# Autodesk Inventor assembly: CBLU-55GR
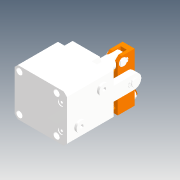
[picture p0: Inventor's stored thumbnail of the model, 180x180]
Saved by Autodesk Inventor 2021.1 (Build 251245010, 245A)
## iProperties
Created: 2019-05
Part Number: CBLU-55GR
Description: STEP AP214
Document SubType Name: Assembly
Designer: user
Title: CBLU-55GR.STEP
Revision Number: ÈÎºÎ
Sending System: SolidWorks 2016
Preprocessor: SwSTEP 2.0
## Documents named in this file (13)
- D:\Vault_2016\Projekty\Clamptek\Hydraulic\CBLU\CBLU-55\Inventor\CBLU-55GR\CBLU-55GR.iam
- D:\Vault_2016\Projekty\Clamptek\Hydraulic\CBLU\CBLU-55\Inventor\CBLU-55GR\CBLU-55CR±¾Ìå_2_1.ipt
- D:\Vault_2016\Projekty\Clamptek\Hydraulic\CBLU\CBLU-55\Inventor\CBLU-55GR\changxiao.ipt
- D:\Vault_2016\Projekty\Clamptek\Hydraulic\CBLU\CBLU-55\Inventor\CBLU-55GR\duanxiao.ipt
- D:\Vault_2016\Projekty\Clamptek\Hydraulic\CBLU\CBLU-55\Inventor\CBLU-55GR\huosaigan_5.ipt
- D:\Vault_2016\Projekty\Clamptek\Hydraulic\CBLU\CBLU-55\Inventor\CBLU-55GR\kahuang.ipt
- D:\Vault_2016\Projekty\Clamptek\Hydraulic\CBLU\CBLU-55\Inventor\CBLU-55GR\kahuang01.ipt
- D:\Vault_2016\Projekty\Clamptek\Hydraulic\CBLU\CBLU-55\Inventor\CBLU-55GR\liangan.ipt
- D:\Vault_2016\Projekty\Clamptek\Hydraulic\CBLU\CBLU-55\Inventor\CBLU-55GR\luogan.ipt
- D:\Vault_2016\Projekty\Clamptek\Hydraulic\CBLU\CBLU-55\Inventor\CBLU-55GR\luomu.ipt
- D:\Vault_2016\Projekty\Clamptek\Hydraulic\CBLU\CBLU-55\Inventor\CBLU-55GR\yabi.ipt
- D:\Vault_2016\Projekty\Clamptek\Hydraulic\CBLU\CBLU-55\Inventor\CBLU-55GR\ÄÚÁù½Ç¶ÂÍ·×îÐÂ1-4_1.ipt
- D:\Vault_2016\Projekty\Clamptek\Hydraulic\CBLU\CBLU-55\Inventor\CBLU-55GR\ÄÚÁù½Ç¶ÂÍ·×îÐÂ1-4_1_2.ipt
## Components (18 placed, 18 different names)
1. CBLU-55CR±¾Ìå_2_1_1
2. changxiao_2
3. duanxiao_3
4. huosaigan_5_4
5. kahuang_5
6. kahuang01_6
7. liangan_7
8. luogan_8
9. luomu_9
10. yabi_10
11. liangan_11
12. changxiao_12
13. kahuang_13
14. kahuang01_14
15. kahuang_15
16. kahuang_16
17. ÄÚÁù½Ç¶ÂÍ·×îÐÂ1-4_1_17
18. ÄÚÁù½Ç¶ÂÍ·×îÐÂ1-4_1_2_18
